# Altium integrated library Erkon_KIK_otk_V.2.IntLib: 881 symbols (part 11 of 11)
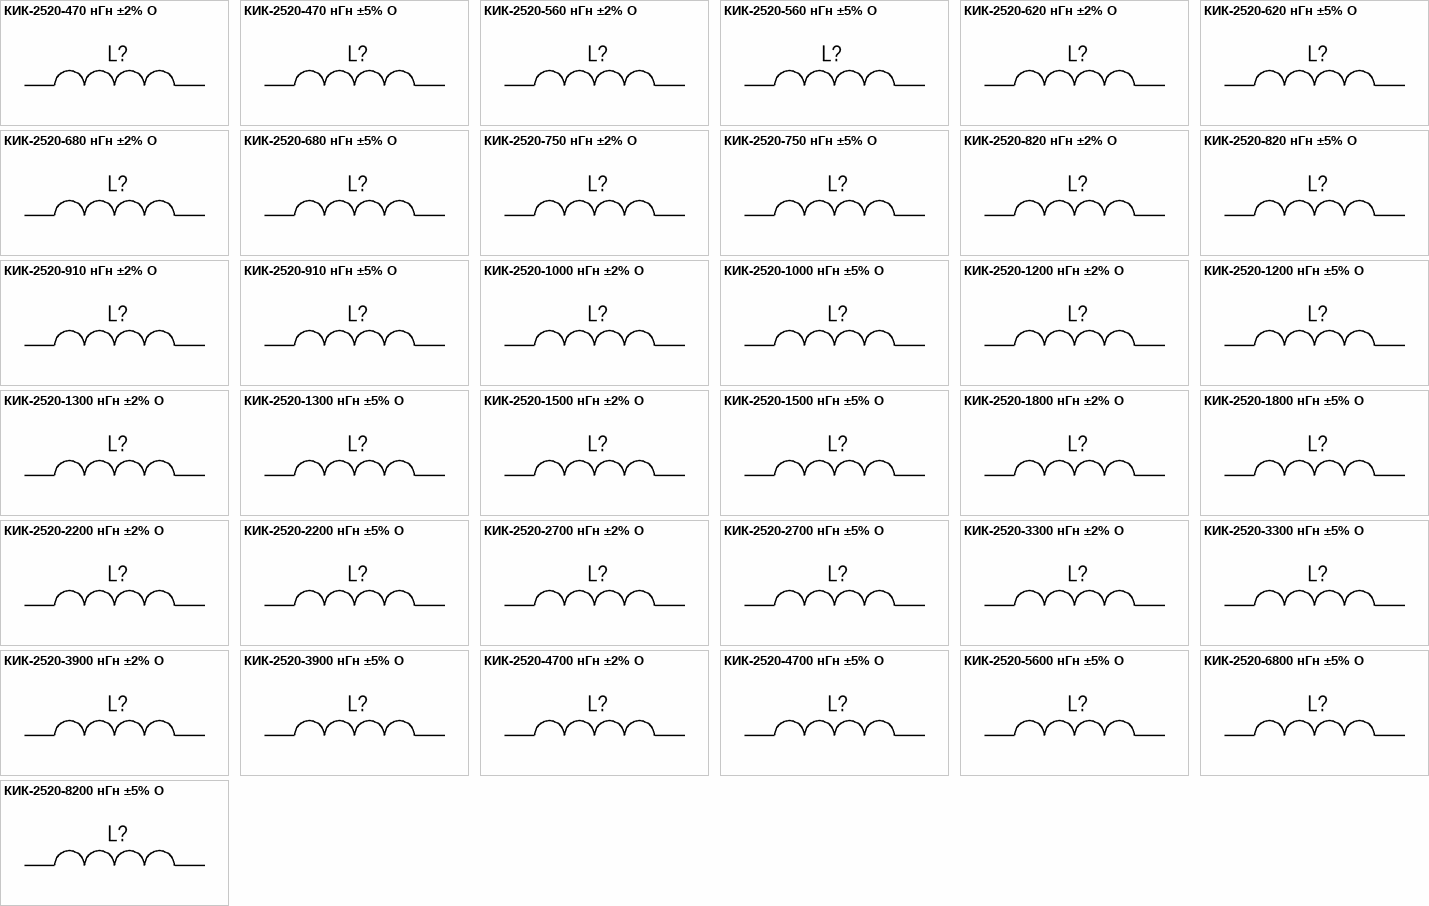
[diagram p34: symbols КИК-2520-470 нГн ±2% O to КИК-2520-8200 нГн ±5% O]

## КИК-2520-820 нГн ±5% O
designator L?, comment 820 нГн ±5%  (value not drawn)
Катушка индуктивности с керамическим сердечником и  финишным покрытием контактных площадок оловом; Номиналиная индуктивность: 820 нГн; Добротность, не менее: 45; Резонансная частота, не менее: 0.350 ГГц; Сопротивление обмотки постоянноми току, не более: 1.61 Ом; Допустимый ток обмотки: 400 мА; Диапазон рабочих температур: от -60 до +125 ℃; Упаковка: Катушка и лента; Типоразмер: 2520 (1008); Технология монтажа: SMT; Изготовитель: АО "НПО "ЭРКОН"
footprint КИК-2520-О (Катушка индуктивности с керамическим сердечником типоразмер 2520(1008))
pins: 1, 2

## КИК-2520-910 нГн ±2% O
designator L?, comment 910 нГн ±2%  (value not drawn)
Катушка индуктивности с керамическим сердечником и  финишным покрытием контактных площадок оловом; Номиналиная индуктивность: 910 нГн; Добротность, не менее: 35; Резонансная частота, не менее: 0.320 ГГц; Сопротивление обмотки постоянноми току, не более: 1.68 Ом; Допустимый ток обмотки: 380 мА; Диапазон рабочих температур: от -60 до +125 ℃; Упаковка: Катушка и лента; Типоразмер: 2520 (1008); Технология монтажа: SMT; Изготовитель: АО "НПО "ЭРКОН"
footprint КИК-2520-О (Катушка индуктивности с керамическим сердечником типоразмер 2520(1008))
pins: 1, 2

## КИК-2520-910 нГн ±5% O
designator L?, comment 910 нГн ±5%  (value not drawn)
Катушка индуктивности с керамическим сердечником и  финишным покрытием контактных площадок оловом; Номиналиная индуктивность: 910 нГн; Добротность, не менее: 35; Резонансная частота, не менее: 0.320 ГГц; Сопротивление обмотки постоянноми току, не более: 1.68 Ом; Допустимый ток обмотки: 380 мА; Диапазон рабочих температур: от -60 до +125 ℃; Упаковка: Катушка и лента; Типоразмер: 2520 (1008); Технология монтажа: SMT; Изготовитель: АО "НПО "ЭРКОН"
footprint КИК-2520-О (Катушка индуктивности с керамическим сердечником типоразмер 2520(1008))
pins: 1, 2

## КИК-2520-1000 нГн ±2% O
designator L?, comment 1000 нГн ±2%  (value not drawn)
Катушка индуктивности с керамическим сердечником и  финишным покрытием контактных площадок оловом; Добротность, не менее: 35; Резонансная частота, не менее: 0.290 ГГц; Сопротивление обмотки постоянноми току, не более: 1.75 Ом; Допустимый ток обмотки: 370 мА; Диапазон рабочих температур: от -60 до +125 ℃; Упаковка: Катушка и лента; Типоразмер: 2520 (1008); Технология монтажа: SMT; Изготовитель: АО "НПО "ЭРКОН"
footprint КИК-2520-О (Катушка индуктивности с керамическим сердечником типоразмер 2520(1008))
pins: 1, 2

## КИК-2520-1000 нГн ±5% O
designator L?, comment 1000 нГн ±5%  (value not drawn)
Катушка индуктивности с керамическим сердечником и  финишным покрытием контактных площадок оловом; Добротность, не менее: 35; Резонансная частота, не менее: 0.290 ГГц; Сопротивление обмотки постоянноми току, не более: 1.75 Ом; Допустимый ток обмотки: 370 мА; Диапазон рабочих температур: от -60 до +125 ℃; Упаковка: Катушка и лента; Типоразмер: 2520 (1008); Технология монтажа: SMT; Изготовитель: АО "НПО "ЭРКОН"
footprint КИК-2520-О (Катушка индуктивности с керамическим сердечником типоразмер 2520(1008))
pins: 1, 2

## КИК-2520-1200 нГн ±2% O
designator L?, comment 1200 нГн ±2%  (value not drawn)
Катушка индуктивности с керамическим сердечником и  финишным покрытием контактных площадок оловом; Добротность, не менее: 35; Резонансная частота, не менее: 0.250 ГГц; Сопротивление обмотки постоянноми току, не более: 2.00 Ом; Допустимый ток обмотки: 310 мА; Диапазон рабочих температур: от -60 до +125 ℃; Упаковка: Катушка и лента; Типоразмер: 2520 (1008); Технология монтажа: SMT; Изготовитель: АО "НПО "ЭРКОН"
footprint КИК-2520-О (Катушка индуктивности с керамическим сердечником типоразмер 2520(1008))
pins: 1, 2

## КИК-2520-1200 нГн ±5% O
designator L?, comment 1200 нГн ±5%  (value not drawn)
Катушка индуктивности с керамическим сердечником и  финишным покрытием контактных площадок оловом; Добротность, не менее: 35; Резонансная частота, не менее: 0.250 ГГц; Сопротивление обмотки постоянноми току, не более: 2.00 Ом; Допустимый ток обмотки: 310 мА; Диапазон рабочих температур: от -60 до +125 ℃; Упаковка: Катушка и лента; Типоразмер: 2520 (1008); Технология монтажа: SMT; Изготовитель: АО "НПО "ЭРКОН"
footprint КИК-2520-О (Катушка индуктивности с керамическим сердечником типоразмер 2520(1008))
pins: 1, 2

## КИК-2520-1300 нГн ±2% O
designator L?, comment 1300 нГн ±2%  (value not drawn)
Катушка индуктивности с керамическим сердечником и  финишным покрытием контактных площадок оловом; Добротность, не менее: 25; Резонансная частота, не менее: 0.200 ГГц; Сопротивление обмотки постоянноми току, не более: 2.25 Ом; Допустимый ток обмотки: 310 мА; Диапазон рабочих температур: от -60 до +125 ℃; Упаковка: Катушка и лента; Типоразмер: 2520 (1008); Технология монтажа: SMT; Изготовитель: АО "НПО "ЭРКОН"
footprint КИК-2520-О (Катушка индуктивности с керамическим сердечником типоразмер 2520(1008))
pins: 1, 2

## КИК-2520-1300 нГн ±5% O
designator L?, comment 1300 нГн ±5%  (value not drawn)
Катушка индуктивности с керамическим сердечником и  финишным покрытием контактных площадок оловом; Добротность, не менее: 25; Резонансная частота, не менее: 0.200 ГГц; Сопротивление обмотки постоянноми току, не более: 2.25 Ом; Допустимый ток обмотки: 310 мА; Диапазон рабочих температур: от -60 до +125 ℃; Упаковка: Катушка и лента; Типоразмер: 2520 (1008); Технология монтажа: SMT; Изготовитель: АО "НПО "ЭРКОН"
footprint КИК-2520-О (Катушка индуктивности с керамическим сердечником типоразмер 2520(1008))
pins: 1, 2

## КИК-2520-1500 нГн ±2% O
designator L?, comment 1500 нГн ±2%  (value not drawn)
Катушка индуктивности с керамическим сердечником и  финишным покрытием контактных площадок оловом; Номиналиная индуктивность: 1300 нГн; Добротность, не менее: 28; Резонансная частота, не менее: 0.200 ГГц; Сопротивление обмотки постоянноми току, не более: 2.30 Ом; Допустимый ток обмотки: 330 мА; Диапазон рабочих температур: от -60 до +125 ℃; Упаковка: Катушка и лента; Типоразмер: 2520 (1008); Технология монтажа: SMT; Изготовитель: АО "НПО "ЭРКОН"
footprint КИК-2520-О (Катушка индуктивности с керамическим сердечником типоразмер 2520(1008))
pins: 1, 2

## КИК-2520-1500 нГн ±5% O
designator L?, comment 1500 нГн ±5%  (value not drawn)
Катушка индуктивности с керамическим сердечником и  финишным покрытием контактных площадок оловом; Номиналиная индуктивность: 1300 нГн; Добротность, не менее: 28; Резонансная частота, не менее: 0.200 ГГц; Сопротивление обмотки постоянноми току, не более: 2.30 Ом; Допустимый ток обмотки: 330 мА; Диапазон рабочих температур: от -60 до +125 ℃; Упаковка: Катушка и лента; Типоразмер: 2520 (1008); Технология монтажа: SMT; Изготовитель: АО "НПО "ЭРКОН"
footprint КИК-2520-О (Катушка индуктивности с керамическим сердечником типоразмер 2520(1008))
pins: 1, 2

## КИК-2520-1800 нГн ±2% O
designator L?, comment 1800 нГн ±2%  (value not drawn)
Катушка индуктивности с керамическим сердечником и  финишным покрытием контактных площадок оловом; Добротность, не менее: 28; Резонансная частота, не менее: 0.160 ГГц; Сопротивление обмотки постоянноми току, не более: 2.60 Ом; Допустимый ток обмотки: 300 мА; Диапазон рабочих температур: от -60 до +125 ℃; Упаковка: Катушка и лента; Типоразмер: 2520 (1008); Технология монтажа: SMT; Изготовитель: АО "НПО "ЭРКОН"
footprint КИК-2520-О (Катушка индуктивности с керамическим сердечником типоразмер 2520(1008))
pins: 1, 2

## КИК-2520-1800 нГн ±5% O
designator L?, comment 1800 нГн ±5%  (value not drawn)
Катушка индуктивности с керамическим сердечником и  финишным покрытием контактных площадок оловом; Добротность, не менее: 28; Резонансная частота, не менее: 0.160 ГГц; Сопротивление обмотки постоянноми току, не более: 2.60 Ом; Допустимый ток обмотки: 300 мА; Диапазон рабочих температур: от -60 до +125 ℃; Упаковка: Катушка и лента; Типоразмер: 2520 (1008); Технология монтажа: SMT; Изготовитель: АО "НПО "ЭРКОН"
footprint КИК-2520-О (Катушка индуктивности с керамическим сердечником типоразмер 2520(1008))
pins: 1, 2

## КИК-2520-2200 нГн ±2% O
designator L?, comment 2200 нГн ±2%  (value not drawn)
Катушка индуктивности с керамическим сердечником и  финишным покрытием контактных площадок оловом; Добротность, не менее: 28; Резонансная частота, не менее: 0.160 ГГц; Сопротивление обмотки постоянноми току, не более: 2.80 Ом; Допустимый ток обмотки: 280 мА; Диапазон рабочих температур: от -60 до +125 ℃; Упаковка: Катушка и лента; Типоразмер: 2520 (1008); Технология монтажа: SMT; Изготовитель: АО "НПО "ЭРКОН"
footprint КИК-2520-О (Катушка индуктивности с керамическим сердечником типоразмер 2520(1008))
pins: 1, 2

## КИК-2520-2200 нГн ±5% O
designator L?, comment 2200 нГн ±5%  (value not drawn)
Катушка индуктивности с керамическим сердечником и  финишным покрытием контактных площадок оловом; Добротность, не менее: 28; Резонансная частота, не менее: 0.160 ГГц; Сопротивление обмотки постоянноми току, не более: 2.80 Ом; Допустимый ток обмотки: 280 мА; Диапазон рабочих температур: от -60 до +125 ℃; Упаковка: Катушка и лента; Типоразмер: 2520 (1008); Технология монтажа: SMT; Изготовитель: АО "НПО "ЭРКОН"
footprint КИК-2520-О (Катушка индуктивности с керамическим сердечником типоразмер 2520(1008))
pins: 1, 2

## КИК-2520-2700 нГн ±2% O
designator L?, comment 2700 нГн ±2%  (value not drawn)
Катушка индуктивности с керамическим сердечником и  финишным покрытием контактных площадок оловом; Добротность, не менее: 22; Резонансная частота, не менее: 0.140 ГГц; Сопротивление обмотки постоянноми току, не более: 3.20 Ом; Допустимый ток обмотки: 290 мА; Диапазон рабочих температур: от -60 до +125 ℃; Упаковка: Катушка и лента; Типоразмер: 2520 (1008); Технология монтажа: SMT; Изготовитель: АО "НПО "ЭРКОН"
footprint КИК-2520-О (Катушка индуктивности с керамическим сердечником типоразмер 2520(1008))
pins: 1, 2

## КИК-2520-2700 нГн ±5% O
designator L?, comment 2700 нГн ±5%  (value not drawn)
Катушка индуктивности с керамическим сердечником и  финишным покрытием контактных площадок оловом; Добротность, не менее: 22; Резонансная частота, не менее: 0.140 ГГц; Сопротивление обмотки постоянноми току, не более: 3.20 Ом; Допустимый ток обмотки: 290 мА; Диапазон рабочих температур: от -60 до +125 ℃; Упаковка: Катушка и лента; Типоразмер: 2520 (1008); Технология монтажа: SMT; Изготовитель: АО "НПО "ЭРКОН"
footprint КИК-2520-О (Катушка индуктивности с керамическим сердечником типоразмер 2520(1008))
pins: 1, 2

## КИК-2520-3300 нГн ±2% O
designator L?, comment 3300 нГн ±2%  (value not drawn)
Катушка индуктивности с керамическим сердечником и  финишным покрытием контактных площадок оловом; Добротность, не менее: 22; Резонансная частота, не менее: 0.110 ГГц; Сопротивление обмотки постоянноми току, не более: 3.40 Ом; Допустимый ток обмотки: 290 мА; Диапазон рабочих температур: от -60 до +125 ℃; Упаковка: Катушка и лента; Типоразмер: 2520 (1008); Технология монтажа: SMT; Изготовитель: АО "НПО "ЭРКОН"
footprint КИК-2520-О (Катушка индуктивности с керамическим сердечником типоразмер 2520(1008))
pins: 1, 2

## КИК-2520-3300 нГн ±5% O
designator L?, comment 3300 нГн ±5%  (value not drawn)
Катушка индуктивности с керамическим сердечником и  финишным покрытием контактных площадок оловом; Добротность, не менее: 22; Резонансная частота, не менее: 0.110 ГГц; Сопротивление обмотки постоянноми току, не более: 3.40 Ом; Допустимый ток обмотки: 290 мА; Диапазон рабочих температур: от -60 до +125 ℃; Упаковка: Катушка и лента; Типоразмер: 2520 (1008); Технология монтажа: SMT; Изготовитель: АО "НПО "ЭРКОН"
footprint КИК-2520-О (Катушка индуктивности с керамическим сердечником типоразмер 2520(1008))
pins: 1, 2

## КИК-2520-3900 нГн ±2% O
designator L?, comment 3900 нГн ±2%  (value not drawn)
Катушка индуктивности с керамическим сердечником и  финишным покрытием контактных площадок оловом; Добротность, не менее: 20; Резонансная частота, не менее: 0.100 ГГц; Сопротивление обмотки постоянноми току, не более: 3.60 Ом; Допустимый ток обмотки: 260 мА; Диапазон рабочих температур: от -60 до +125 ℃; Упаковка: Катушка и лента; Типоразмер: 2520 (1008); Технология монтажа: SMT; Изготовитель: АО "НПО "ЭРКОН"
footprint КИК-2520-О (Катушка индуктивности с керамическим сердечником типоразмер 2520(1008))
pins: 1, 2

## КИК-2520-3900 нГн ±5% O
designator L?, comment 3900 нГн ±5%  (value not drawn)
Катушка индуктивности с керамическим сердечником и  финишным покрытием контактных площадок оловом; Добротность, не менее: 20; Резонансная частота, не менее: 0.100 ГГц; Сопротивление обмотки постоянноми току, не более: 3.60 Ом; Допустимый ток обмотки: 260 мА; Диапазон рабочих температур: от -60 до +125 ℃; Упаковка: Катушка и лента; Типоразмер: 2520 (1008); Технология монтажа: SMT; Изготовитель: АО "НПО "ЭРКОН"
footprint КИК-2520-О (Катушка индуктивности с керамическим сердечником типоразмер 2520(1008))
pins: 1, 2

## КИК-2520-4700 нГн ±2% O
designator L?, comment 4700 нГн ±2%  (value not drawn)
Катушка индуктивности с керамическим сердечником и  финишным покрытием контактных площадок оловом; Добротность, не менее: 20; Резонансная частота, не менее: 0.090 ГГц; Сопротивление обмотки постоянноми току, не более: 4.00 Ом; Допустимый ток обмотки: 260 мА; Диапазон рабочих температур: от -60 до +125 ℃; Упаковка: Катушка и лента; Типоразмер: 2520 (1008); Технология монтажа: SMT; Изготовитель: АО "НПО "ЭРКОН"
footprint КИК-2520-О (Катушка индуктивности с керамическим сердечником типоразмер 2520(1008))
pins: 1, 2

## КИК-2520-4700 нГн ±5% O
designator L?, comment 4700 нГн ±5%  (value not drawn)
Катушка индуктивности с керамическим сердечником и  финишным покрытием контактных площадок оловом; Добротность, не менее: 20; Резонансная частота, не менее: 0.090 ГГц; Сопротивление обмотки постоянноми току, не более: 4.00 Ом; Допустимый ток обмотки: 260 мА; Диапазон рабочих температур: от -60 до +125 ℃; Упаковка: Катушка и лента; Типоразмер: 2520 (1008); Технология монтажа: SMT; Изготовитель: АО "НПО "ЭРКОН"
footprint КИК-2520-О (Катушка индуктивности с керамическим сердечником типоразмер 2520(1008))
pins: 1, 2

## КИК-2520-5600 нГн ±5% O
designator L?, comment 5600 нГн ±5%  (value not drawn)
Катушка индуктивности с керамическим сердечником и  финишным покрытием контактных площадок оловом; Добротность, не менее: 16; Резонансная частота, не менее: 0.020 ГГц; Сопротивление обмотки постоянноми току, не более: 4.00 Ом; Допустимый ток обмотки: 240 мА; Диапазон рабочих температур: от -60 до +125 ℃; Упаковка: Катушка и лента; Типоразмер: 2520 (1008); Технология монтажа: SMT; Изготовитель: АО "НПО "ЭРКОН"
footprint КИК-2520-О (Катушка индуктивности с керамическим сердечником типоразмер 2520(1008))
pins: 1, 2

## КИК-2520-6800 нГн ±5% O
designator L?, comment 6800 нГн ±5%  (value not drawn)
Катушка индуктивности с керамическим сердечником и  финишным покрытием контактных площадок оловом; Добротность, не менее: 18; Резонансная частота, не менее: 0.040 ГГц; Сопротивление обмотки постоянноми току, не более: 4.90 Ом; Допустимый ток обмотки: 200 мА; Диапазон рабочих температур: от -60 до +125 ℃; Упаковка: Катушка и лента; Типоразмер: 2520 (1008); Технология монтажа: SMT; Изготовитель: АО "НПО "ЭРКОН"
footprint КИК-2520-О (Катушка индуктивности с керамическим сердечником типоразмер 2520(1008))
pins: 1, 2

## КИК-2520-8200 нГн ±5% O
designator L?, comment 8200 нГн ±5%  (value not drawn)
Катушка индуктивности с керамическим сердечником и  финишным покрытием контактных площадок оловом; Добротность, не менее: 18; Резонансная частота, не менее: 0.025 ГГц; Сопротивление обмотки постоянноми току, не более: 6.00 Ом; Допустимый ток обмотки: 170 мА; Диапазон рабочих температур: от -60 до +125 ℃; Упаковка: Катушка и лента; Типоразмер: 2520 (1008); Технология монтажа: SMT; Изготовитель: АО "НПО "ЭРКОН"
footprint КИК-2520-О (Катушка индуктивности с керамическим сердечником типоразмер 2520(1008))
pins: 1, 2


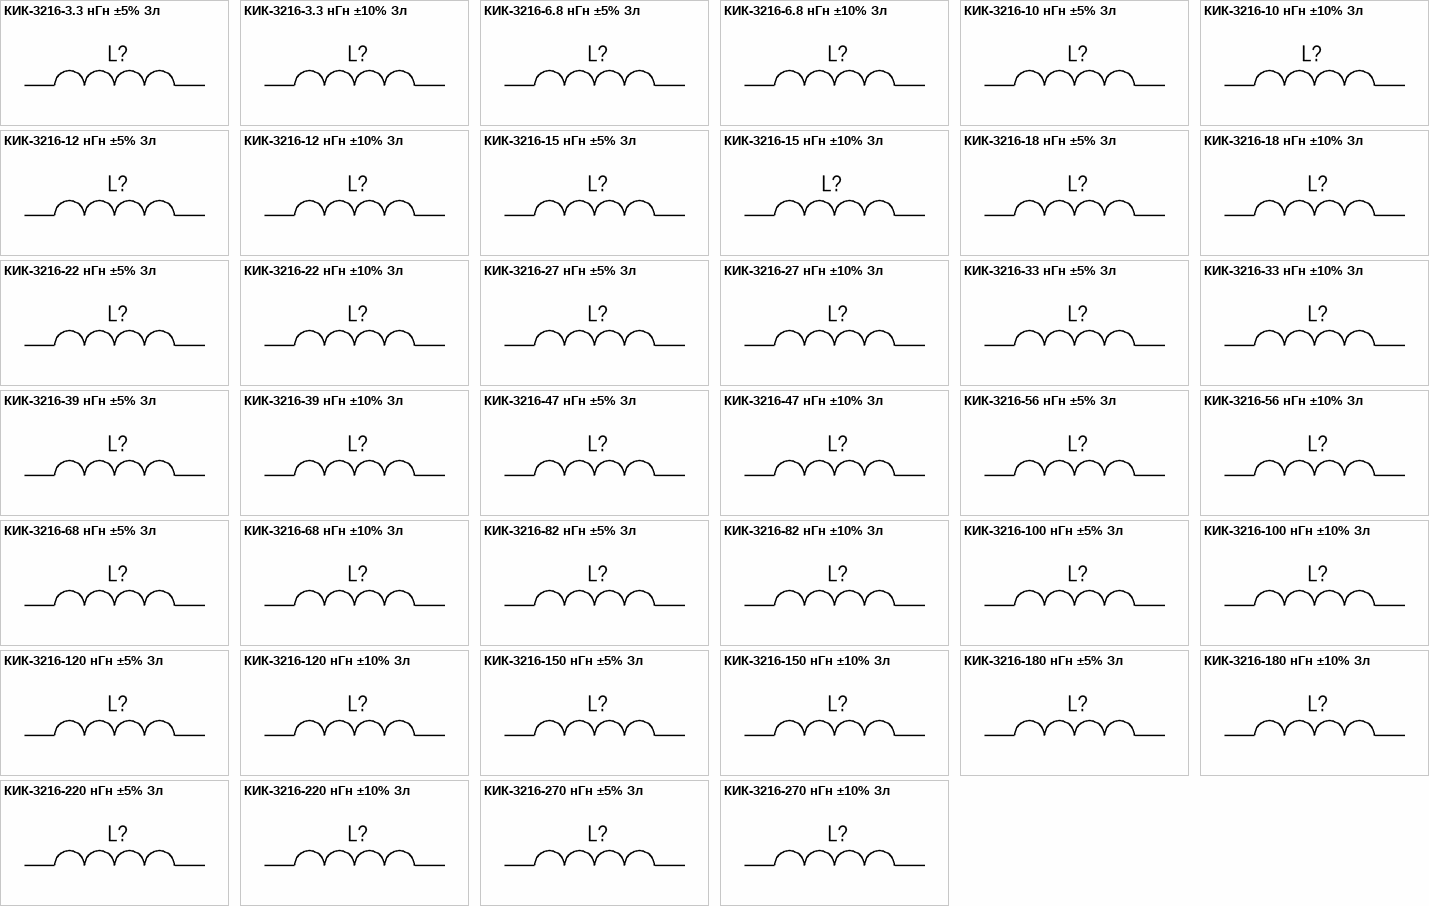
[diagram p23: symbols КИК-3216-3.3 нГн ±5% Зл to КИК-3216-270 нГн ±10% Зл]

## КИК-3216-3.3 нГн ±5% Зл
designator L?, comment 3.3 нГн ±5%  (value not drawn)
Катушка индуктивности с керамическим сердечником и золотым покрытием контактных площадок; Номиналиная индуктивность: 3.3 нГн; Добротность, не менее: 30; Резонансная частота, не менее: 6.20 ГГц; Сопротивление обмотки постоянноми току, не более: 0.05 Ом; Допустимый ток обмотки: 1000 мА; Диапазон рабочих температур: от -60 до +125 ℃; Упаковка: Катушка и лента; Типоразмер: 3216 (1206); Технология монтажа: SMT; Изготовитель: АО "НПО "ЭРКОН"
pins: 1, 2

## КИК-3216-3.3 нГн ±10% Зл
designator L?, comment 3.3 нГн ±10%  (value not drawn)
Катушка индуктивности с керамическим сердечником и золотым покрытием контактных площадок; Номиналиная индуктивность: 3.3 нГн; Добротность, не менее: 30; Резонансная частота, не менее: 6.20 ГГц; Сопротивление обмотки постоянноми току, не более: 0.05 Ом; Допустимый ток обмотки: 1000 мА; Диапазон рабочих температур: от -60 до +125 ℃; Упаковка: Катушка и лента; Типоразмер: 3216 (1206); Технология монтажа: SMT; Изготовитель: АО "НПО "ЭРКОН"
pins: 1, 2

## КИК-3216-6.8 нГн ±5% Зл
designator L?, comment 6.8 нГн ±5%  (value not drawn)
Катушка индуктивности с керамическим сердечником и золотым покрытием контактных площадок; Номиналиная индуктивность: 6.8 нГн; Добротность, не менее: 30; Резонансная частота, не менее: 5.50 ГГц; Сопротивление обмотки постоянноми току, не более: 0.07 Ом; Допустимый ток обмотки: 1000 мА; Диапазон рабочих температур: от -60 до +125 ℃; Упаковка: Катушка и лента; Типоразмер: 3216 (1206); Технология монтажа: SMT; Изготовитель: АО "НПО "ЭРКОН"
pins: 1, 2

## КИК-3216-6.8 нГн ±10% Зл
designator L?, comment 6.8 нГн ±10%  (value not drawn)
Катушка индуктивности с керамическим сердечником и золотым покрытием контактных площадок; Номиналиная индуктивность: 6.8 нГн; Добротность, не менее: 30; Резонансная частота, не менее: 5.50 ГГц; Сопротивление обмотки постоянноми току, не более: 0.07 Ом; Допустимый ток обмотки: 1000 мА; Диапазон рабочих температур: от -60 до +125 ℃; Упаковка: Катушка и лента; Типоразмер: 3216 (1206); Технология монтажа: SMT; Изготовитель: АО "НПО "ЭРКОН"
pins: 1, 2

## КИК-3216-10 нГн ±5% Зл
designator L?, comment 10 нГн ±5%  (value not drawn)
Катушка индуктивности с керамическим сердечником и золотым покрытием контактных площадок; Номиналиная индуктивность: 10 нГн; Добротность, не менее: 40; Резонансная частота, не менее: 4.0 ГГц; Сопротивление обмотки постоянноми току, не более: 0.08 Ом; Допустимый ток обмотки: 1000 мА; Диапазон рабочих температур: от -60 до +125 ℃; Упаковка: Катушка и лента; Типоразмер: 3216 (1206); Технология монтажа: SMT; Изготовитель: АО "НПО "ЭРКОН"
pins: 1, 2

## КИК-3216-10 нГн ±10% Зл
designator L?, comment 10 нГн ±10%  (value not drawn)
Катушка индуктивности с керамическим сердечником и золотым покрытием контактных площадок; Номиналиная индуктивность: 10 нГн; Добротность, не менее: 40; Резонансная частота, не менее: 4.0 ГГц; Сопротивление обмотки постоянноми току, не более: 0.08 Ом; Допустимый ток обмотки: 1000 мА; Диапазон рабочих температур: от -60 до +125 ℃; Упаковка: Катушка и лента; Типоразмер: 3216 (1206); Технология монтажа: SMT; Изготовитель: АО "НПО "ЭРКОН"
pins: 1, 2

## КИК-3216-12 нГн ±5% Зл
designator L?, comment 12 нГн ±5%  (value not drawn)
Катушка индуктивности с керамическим сердечником и золотым покрытием контактных площадок; Номиналиная индуктивность: 12 нГн; Добротность, не менее: 40; Резонансная частота, не менее: 3.20 ГГц; Сопротивление обмотки постоянноми току, не более: 0.08 Ом; Допустимый ток обмотки: 1000 мА; Диапазон рабочих температур: от -60 до +125 ℃; Упаковка: Катушка и лента; Типоразмер: 3216 (1206); Технология монтажа: SMT; Изготовитель: АО "НПО "ЭРКОН"
pins: 1, 2

## КИК-3216-12 нГн ±10% Зл
designator L?, comment 12 нГн ±10%  (value not drawn)
Катушка индуктивности с керамическим сердечником и золотым покрытием контактных площадок; Номиналиная индуктивность: 12 нГн; Добротность, не менее: 40; Резонансная частота, не менее: 3.20 ГГц; Сопротивление обмотки постоянноми току, не более: 0.08 Ом; Допустимый ток обмотки: 1000 мА; Диапазон рабочих температур: от -60 до +125 ℃; Упаковка: Катушка и лента; Типоразмер: 3216 (1206); Технология монтажа: SMT; Изготовитель: АО "НПО "ЭРКОН"
pins: 1, 2

## КИК-3216-15 нГн ±5% Зл
designator L?, comment 15 нГн ±5%  (value not drawn)
Катушка индуктивности с керамическим сердечником и золотым покрытием контактных площадок; Номиналиная индуктивность: 15 нГн; Добротность, не менее: 40; Резонансная частота, не менее: 3.20 ГГц; Сопротивление обмотки постоянноми току, не более: 0.10 Ом; Допустимый ток обмотки: 1000 мА; Диапазон рабочих температур: от -60 до +125 ℃; Упаковка: Катушка и лента; Типоразмер: 3216 (1206); Технология монтажа: SMT; Изготовитель: АО "НПО "ЭРКОН"
pins: 1, 2

## КИК-3216-15 нГн ±10% Зл
designator L?, comment 15 нГн ±10%  (value not drawn)
Катушка индуктивности с керамическим сердечником и золотым покрытием контактных площадок; Номиналиная индуктивность: 15 нГн; Добротность, не менее: 40; Резонансная частота, не менее: 3.20 ГГц; Сопротивление обмотки постоянноми току, не более: 0.10 Ом; Допустимый ток обмотки: 1000 мА; Диапазон рабочих температур: от -60 до +125 ℃; Упаковка: Катушка и лента; Типоразмер: 3216 (1206); Технология монтажа: SMT; Изготовитель: АО "НПО "ЭРКОН"
pins: 1, 2

## КИК-3216-18 нГн ±5% Зл
designator L?, comment 18 нГн ±5%  (value not drawn)
Катушка индуктивности с керамическим сердечником и золотым покрытием контактных площадок; Номиналиная индуктивность: 18 нГн; Добротность, не менее: 50; Резонансная частота, не менее: 2.80 ГГц; Сопротивление обмотки постоянноми току, не более: 0.10 Ом; Допустимый ток обмотки: 1000 мА; Диапазон рабочих температур: от -60 до +125 ℃; Упаковка: Катушка и лента; Типоразмер: 3216 (1206); Технология монтажа: SMT; Изготовитель: АО "НПО "ЭРКОН"
pins: 1, 2

## КИК-3216-18 нГн ±10% Зл
designator L?, comment 18 нГн ±10%  (value not drawn)
Катушка индуктивности с керамическим сердечником и золотым покрытием контактных площадок; Номиналиная индуктивность: 18 нГн; Добротность, не менее: 50; Резонансная частота, не менее: 2.80 ГГц; Сопротивление обмотки постоянноми току, не более: 0.10 Ом; Допустимый ток обмотки: 1000 мА; Диапазон рабочих температур: от -60 до +125 ℃; Упаковка: Катушка и лента; Типоразмер: 3216 (1206); Технология монтажа: SMT; Изготовитель: АО "НПО "ЭРКОН"
pins: 1, 2

## КИК-3216-22 нГн ±5% Зл
designator L?, comment 22 нГн ±5%  (value not drawn)
Катушка индуктивности с керамическим сердечником и золотым покрытием контактных площадок; Номиналиная индуктивность: 22 нГн; Добротность, не менее: 50; Резонансная частота, не менее: 2.20 ГГц; Сопротивление обмотки постоянноми току, не более: 0.10 Ом; Допустимый ток обмотки: 1000 мА; Диапазон рабочих температур: от -60 до +125 ℃; Упаковка: Катушка и лента; Типоразмер: 3216 (1206); Технология монтажа: SMT; Изготовитель: АО "НПО "ЭРКОН"
pins: 1, 2

## КИК-3216-22 нГн ±10% Зл
designator L?, comment 22 нГн ±10%  (value not drawn)
Катушка индуктивности с керамическим сердечником и золотым покрытием контактных площадок; Номиналиная индуктивность: 22 нГн; Добротность, не менее: 50; Резонансная частота, не менее: 2.20 ГГц; Сопротивление обмотки постоянноми току, не более: 0.10 Ом; Допустимый ток обмотки: 1000 мА; Диапазон рабочих температур: от -60 до +125 ℃; Упаковка: Катушка и лента; Типоразмер: 3216 (1206); Технология монтажа: SMT; Изготовитель: АО "НПО "ЭРКОН"
pins: 1, 2

## КИК-3216-27 нГн ±5% Зл
designator L?, comment 27 нГн ±5%  (value not drawn)
Катушка индуктивности с керамическим сердечником и золотым покрытием контактных площадок; Номиналиная индуктивность: 27 нГн; Добротность, не менее: 50; Резонансная частота, не менее: 1.80 ГГц; Сопротивление обмотки постоянноми току, не более: 0.11 Ом; Допустимый ток обмотки: 1000 мА; Диапазон рабочих температур: от -60 до +125 ℃; Упаковка: Катушка и лента; Типоразмер: 3216 (1206); Технология монтажа: SMT; Изготовитель: АО "НПО "ЭРКОН"
pins: 1, 2

## КИК-3216-27 нГн ±10% Зл
designator L?, comment 27 нГн ±10%  (value not drawn)
Катушка индуктивности с керамическим сердечником и золотым покрытием контактных площадок; Номиналиная индуктивность: 27 нГн; Добротность, не менее: 50; Резонансная частота, не менее: 1.80 ГГц; Сопротивление обмотки постоянноми току, не более: 0.11 Ом; Допустимый ток обмотки: 1000 мА; Диапазон рабочих температур: от -60 до +125 ℃; Упаковка: Катушка и лента; Типоразмер: 3216 (1206); Технология монтажа: SMT; Изготовитель: АО "НПО "ЭРКОН"
pins: 1, 2

## КИК-3216-33 нГн ±5% Зл
designator L?, comment 33 нГн ±5%  (value not drawn)
Катушка индуктивности с керамическим сердечником и золотым покрытием контактных площадок; Номиналиная индуктивность: 33 нГн; Добротность, не менее: 55; Резонансная частота, не менее: 1.80 ГГц; Сопротивление обмотки постоянноми току, не более: 0.11 Ом; Допустимый ток обмотки: 1000 мА; Диапазон рабочих температур: от -60 до +125 ℃; Упаковка: Катушка и лента; Типоразмер: 3216 (1206); Технология монтажа: SMT; Изготовитель: АО "НПО "ЭРКОН"
pins: 1, 2

## КИК-3216-33 нГн ±10% Зл
designator L?, comment 33 нГн ±10%  (value not drawn)
Катушка индуктивности с керамическим сердечником и золотым покрытием контактных площадок; Номиналиная индуктивность: 33 нГн; Добротность, не менее: 55; Резонансная частота, не менее: 1.80 ГГц; Сопротивление обмотки постоянноми току, не более: 0.11 Ом; Допустимый ток обмотки: 1000 мА; Диапазон рабочих температур: от -60 до +125 ℃; Упаковка: Катушка и лента; Типоразмер: 3216 (1206); Технология монтажа: SMT; Изготовитель: АО "НПО "ЭРКОН"
pins: 1, 2

## КИК-3216-39 нГн ±5% Зл
designator L?, comment 39 нГн ±5%  (value not drawn)
Катушка индуктивности с керамическим сердечником и золотым покрытием контактных площадок; Номиналиная индуктивность: 39 нГн; Добротность, не менее: 55; Резонансная частота, не менее: 1.80 ГГц; Сопротивление обмотки постоянноми току, не более: 0.12 Ом; Допустимый ток обмотки: 1000 мА; Диапазон рабочих температур: от -60 до +125 ℃; Упаковка: Катушка и лента; Типоразмер: 3216 (1206); Технология монтажа: SMT; Изготовитель: АО "НПО "ЭРКОН"
pins: 1, 2

## КИК-3216-39 нГн ±10% Зл
designator L?, comment 39 нГн ±10%  (value not drawn)
Катушка индуктивности с керамическим сердечником и золотым покрытием контактных площадок; Номиналиная индуктивность: 39 нГн; Добротность, не менее: 55; Резонансная частота, не менее: 1.80 ГГц; Сопротивление обмотки постоянноми току, не более: 0.12 Ом; Допустимый ток обмотки: 1000 мА; Диапазон рабочих температур: от -60 до +125 ℃; Упаковка: Катушка и лента; Типоразмер: 3216 (1206); Технология монтажа: SMT; Изготовитель: АО "НПО "ЭРКОН"
pins: 1, 2

## КИК-3216-47 нГн ±5% Зл
designator L?, comment 47 нГн ±5%  (value not drawn)
Катушка индуктивности с керамическим сердечником и золотым покрытием контактных площадок; Номиналиная индуктивность: 47 нГн; Добротность, не менее: 55; Резонансная частота, не менее: 1.50 ГГц; Сопротивление обмотки постоянноми току, не более: 0.13 Ом; Допустимый ток обмотки: 1000 мА; Диапазон рабочих температур: от -60 до +125 ℃; Упаковка: Катушка и лента; Типоразмер: 3216 (1206); Технология монтажа: SMT; Изготовитель: АО "НПО "ЭРКОН"
pins: 1, 2

## КИК-3216-47 нГн ±10% Зл
designator L?, comment 47 нГн ±10%  (value not drawn)
Катушка индуктивности с керамическим сердечником и золотым покрытием контактных площадок; Номиналиная индуктивность: 47 нГн; Добротность, не менее: 55; Резонансная частота, не менее: 1.50 ГГц; Сопротивление обмотки постоянноми току, не более: 0.13 Ом; Допустимый ток обмотки: 1000 мА; Диапазон рабочих температур: от -60 до +125 ℃; Упаковка: Катушка и лента; Типоразмер: 3216 (1206); Технология монтажа: SMT; Изготовитель: АО "НПО "ЭРКОН"
pins: 1, 2

## КИК-3216-56 нГн ±5% Зл
designator L?, comment 56 нГн ±5%  (value not drawn)
Катушка индуктивности с керамическим сердечником и золотым покрытием контактных площадок; Номиналиная индуктивность: 56 нГн; Добротность, не менее: 55; Резонансная частота, не менее: 1.45 ГГц; Сопротивление обмотки постоянноми току, не более: 0.14 Ом; Допустимый ток обмотки: 1000 мА; Диапазон рабочих температур: от -60 до +125 ℃; Упаковка: Катушка и лента; Типоразмер: 3216 (1206); Технология монтажа: SMT; Изготовитель: АО "НПО "ЭРКОН"
pins: 1, 2

## КИК-3216-56 нГн ±10% Зл
designator L?, comment 56 нГн ±10%  (value not drawn)
Катушка индуктивности с керамическим сердечником и золотым покрытием контактных площадок; Номиналиная индуктивность: 56 нГн; Добротность, не менее: 55; Резонансная частота, не менее: 1.45 ГГц; Сопротивление обмотки постоянноми току, не более: 0.14 Ом; Допустимый ток обмотки: 1000 мА; Диапазон рабочих температур: от -60 до +125 ℃; Упаковка: Катушка и лента; Типоразмер: 3216 (1206); Технология монтажа: SMT; Изготовитель: АО "НПО "ЭРКОН"
pins: 1, 2

## КИК-3216-68 нГн ±5% Зл
designator L?, comment 68 нГн ±5%  (value not drawn)
Катушка индуктивности с керамическим сердечником и золотым покрытием контактных площадок; Номиналиная индуктивность: 68 нГн; Добротность, не менее: 55; Резонансная частота, не менее: 1.20 ГГц; Сопротивление обмотки постоянноми току, не более: 0.26 Ом; Допустимый ток обмотки: 900 мА; Диапазон рабочих температур: от -60 до +125 ℃; Упаковка: Катушка и лента; Типоразмер: 3216 (1206); Технология монтажа: SMT; Изготовитель: АО "НПО "ЭРКОН"
pins: 1, 2

## КИК-3216-68 нГн ±10% Зл
designator L?, comment 68 нГн ±10%  (value not drawn)
Катушка индуктивности с керамическим сердечником и золотым покрытием контактных площадок; Номиналиная индуктивность: 68 нГн; Добротность, не менее: 55; Резонансная частота, не менее: 1.20 ГГц; Сопротивление обмотки постоянноми току, не более: 0.26 Ом; Допустимый ток обмотки: 900 мА; Диапазон рабочих температур: от -60 до +125 ℃; Упаковка: Катушка и лента; Типоразмер: 3216 (1206); Технология монтажа: SMT; Изготовитель: АО "НПО "ЭРКОН"
pins: 1, 2

## КИК-3216-82 нГн ±5% Зл
designator L?, comment 82 нГн ±5%  (value not drawn)
Катушка индуктивности с керамическим сердечником и золотым покрытием контактных площадок; Номиналиная индуктивность: 82 нГн; Добротность, не менее: 55; Резонансная частота, не менее: 1.20 ГГц; Сопротивление обмотки постоянноми току, не более: 0.21 Ом; Допустимый ток обмотки: 900 мА; Диапазон рабочих температур: от -60 до +125 ℃; Упаковка: Катушка и лента; Типоразмер: 3216 (1206); Технология монтажа: SMT; Изготовитель: АО "НПО "ЭРКОН"
pins: 1, 2

## КИК-3216-82 нГн ±10% Зл
designator L?, comment 82 нГн ±10%  (value not drawn)
Катушка индуктивности с керамическим сердечником и золотым покрытием контактных площадок; Номиналиная индуктивность: 82 нГн; Добротность, не менее: 55; Резонансная частота, не менее: 1.20 ГГц; Сопротивление обмотки постоянноми току, не более: 0.21 Ом; Допустимый ток обмотки: 900 мА; Диапазон рабочих температур: от -60 до +125 ℃; Упаковка: Катушка и лента; Типоразмер: 3216 (1206); Технология монтажа: SMT; Изготовитель: АО "НПО "ЭРКОН"
pins: 1, 2

## КИК-3216-100 нГн ±5% Зл
designator L?, comment 100 нГн ±5%  (value not drawn)
Катушка индуктивности с керамическим сердечником и золотым покрытием контактных площадок; Номиналиная индуктивность: 100 нГн; Добротность, не менее: 55; Резонансная частота, не менее: 1.10 ГГц; Сопротивление обмотки постоянноми току, не более: 0.26 Ом; Допустимый ток обмотки: 850 мА; Диапазон рабочих температур: от -60 до +125 ℃; Упаковка: Катушка и лента; Типоразмер: 3216 (1206); Технология монтажа: SMT; Изготовитель: АО "НПО "ЭРКОН"
pins: 1, 2

## КИК-3216-100 нГн ±10% Зл
designator L?, comment 100 нГн ±10%  (value not drawn)
Катушка индуктивности с керамическим сердечником и золотым покрытием контактных площадок; Номиналиная индуктивность: 100 нГн; Добротность, не менее: 55; Резонансная частота, не менее: 1.10 ГГц; Сопротивление обмотки постоянноми току, не более: 0.26 Ом; Допустимый ток обмотки: 850 мА; Диапазон рабочих температур: от -60 до +125 ℃; Упаковка: Катушка и лента; Типоразмер: 3216 (1206); Технология монтажа: SMT; Изготовитель: АО "НПО "ЭРКОН"
pins: 1, 2

## КИК-3216-120 нГн ±5% Зл
designator L?, comment 120 нГн ±5%  (value not drawn)
Катушка индуктивности с керамическим сердечником и золотым покрытием контактных площадок; Номиналиная индуктивность: 120 нГн; Добротность, не менее: 55; Резонансная частота, не менее: 1.10 ГГц; Сопротивление обмотки постоянноми току, не более: 0.26 Ом; Допустимый ток обмотки: 800 мА; Диапазон рабочих температур: от -60 до +125 ℃; Упаковка: Катушка и лента; Типоразмер: 3216 (1206); Технология монтажа: SMT; Изготовитель: АО "НПО "ЭРКОН"
pins: 1, 2

## КИК-3216-120 нГн ±10% Зл
designator L?, comment 120 нГн ±10%  (value not drawn)
Катушка индуктивности с керамическим сердечником и золотым покрытием контактных площадок; Номиналиная индуктивность: 120 нГн; Добротность, не менее: 60; Резонансная частота, не менее: 1.10 ГГц; Сопротивление обмотки постоянноми току, не более: 0.26 Ом; Допустимый ток обмотки: 800 мА; Диапазон рабочих температур: от -60 до +125 ℃; Упаковка: Катушка и лента; Типоразмер: 3216 (1206); Технология монтажа: SMT; Изготовитель: АО "НПО "ЭРКОН"
pins: 1, 2

## КИК-3216-150 нГн ±5% Зл
designator L?, comment 150 нГн ±5%  (value not drawn)
Катушка индуктивности с керамическим сердечником и золотым покрытием контактных площадок; Номиналиная индуктивность: 150 нГн; Добротность, не менее: 60; Резонансная частота, не менее: 0.95 ГГц; Сопротивление обмотки постоянноми току, не более: 0.31 Ом; Допустимый ток обмотки: 750 мА; Диапазон рабочих температур: от -60 до +125 ℃; Упаковка: Катушка и лента; Типоразмер: 3216 (1206); Технология монтажа: SMT; Изготовитель: АО "НПО "ЭРКОН"
pins: 1, 2

## КИК-3216-150 нГн ±10% Зл
designator L?, comment 150 нГн ±10%  (value not drawn)
Катушка индуктивности с керамическим сердечником и золотым покрытием контактных площадок; Номиналиная индуктивность: 150 нГн; Добротность, не менее: 60; Резонансная частота, не менее: 0.95 ГГц; Сопротивление обмотки постоянноми току, не более: 0.31 Ом; Допустимый ток обмотки: 750 мА; Диапазон рабочих температур: от -60 до +125 ℃; Упаковка: Катушка и лента; Типоразмер: 3216 (1206); Технология монтажа: SMT; Изготовитель: АО "НПО "ЭРКОН"
pins: 1, 2

## КИК-3216-180 нГн ±5% Зл
designator L?, comment 180 нГн ±5%  (value not drawn)
Катушка индуктивности с керамическим сердечником и золотым покрытием контактных площадок; Номиналиная индуктивность: 180 нГн; Добротность, не менее: 60; Резонансная частота, не менее: 0.90 ГГц; Сопротивление обмотки постоянноми току, не более: 0.43 Ом; Допустимый ток обмотки: 700 мА; Диапазон рабочих температур: от -60 до +125 ℃; Упаковка: Катушка и лента; Типоразмер: 3216 (1206); Технология монтажа: SMT; Изготовитель: АО "НПО "ЭРКОН"
pins: 1, 2

## КИК-3216-180 нГн ±10% Зл
designator L?, comment 180 нГн ±10%  (value not drawn)
Катушка индуктивности с керамическим сердечником и золотым покрытием контактных площадок; Номиналиная индуктивность: 180 нГн; Добротность, не менее: 60; Резонансная частота, не менее: 0.90 ГГц; Сопротивление обмотки постоянноми току, не более: 0.43 Ом; Допустимый ток обмотки: 700 мА; Диапазон рабочих температур: от -60 до +125 ℃; Упаковка: Катушка и лента; Типоразмер: 3216 (1206); Технология монтажа: SMT; Изготовитель: АО "НПО "ЭРКОН"
pins: 1, 2

## КИК-3216-220 нГн ±5% Зл
designator L?, comment 220 нГн ±5%  (value not drawn)
Катушка индуктивности с керамическим сердечником и золотым покрытием контактных площадок; Номиналиная индуктивность: 220 нГн; Добротность, не менее: 60; Резонансная частота, не менее: 0.76 ГГц; Сопротивление обмотки постоянноми току, не более: 0.50 Ом; Допустимый ток обмотки: 670 мА; Диапазон рабочих температур: от -60 до +125 ℃; Упаковка: Катушка и лента; Типоразмер: 3216 (1206); Технология монтажа: SMT; Изготовитель: АО "НПО "ЭРКОН"
pins: 1, 2

## КИК-3216-220 нГн ±10% Зл
designator L?, comment 220 нГн ±10%  (value not drawn)
Катушка индуктивности с керамическим сердечником и золотым покрытием контактных площадок; Номиналиная индуктивность: 220 нГн; Добротность, не менее: 60; Резонансная частота, не менее: 0.76 ГГц; Сопротивление обмотки постоянноми току, не более: 0.50 Ом; Допустимый ток обмотки: 670 мА; Диапазон рабочих температур: от -60 до +125 ℃; Упаковка: Катушка и лента; Типоразмер: 3216 (1206); Технология монтажа: SMT; Изготовитель: АО "НПО "ЭРКОН"
pins: 1, 2

## КИК-3216-270 нГн ±5% Зл
designator L?, comment 270 нГн ±5%  (value not drawn)
Катушка индуктивности с керамическим сердечником и золотым покрытием контактных площадок; Номиналиная индуктивность: 270 нГн; Добротность, не менее: 55; Резонансная частота, не менее: 0.73 ГГц; Сопротивление обмотки постоянноми току, не более: 0.56 Ом; Допустимый ток обмотки: 630 мА; Диапазон рабочих температур: от -60 до +125 ℃; Упаковка: Катушка и лента; Типоразмер: 3216 (1206); Технология монтажа: SMT; Изготовитель: АО "НПО "ЭРКОН"
pins: 1, 2

## КИК-3216-270 нГн ±10% Зл
designator L?, comment 270 нГн ±10%  (value not drawn)
Катушка индуктивности с керамическим сердечником и золотым покрытием контактных площадок; Номиналиная индуктивность: 270 нГн; Добротность, не менее: 55; Резонансная частота, не менее: 0.73 ГГц; Сопротивление обмотки постоянноми току, не более: 0.56 Ом; Допустимый ток обмотки: 630 мА; Диапазон рабочих температур: от -60 до +125 ℃; Упаковка: Катушка и лента; Типоразмер: 3216 (1206); Технология монтажа: SMT; Изготовитель: АО "НПО "ЭРКОН"
pins: 1, 2

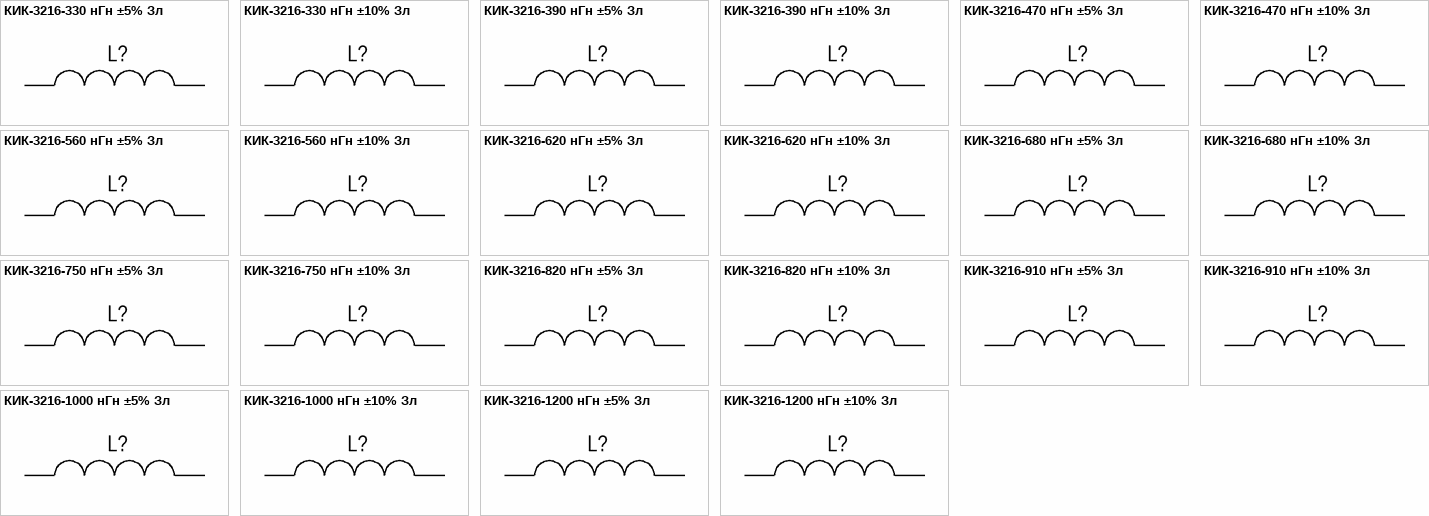
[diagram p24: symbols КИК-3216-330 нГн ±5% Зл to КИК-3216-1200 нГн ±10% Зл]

## КИК-3216-330 нГн ±5% Зл
designator L?, comment 330 нГн ±5%  (value not drawn)
Катушка индуктивности с керамическим сердечником и золотым покрытием контактных площадок; Номиналиная индуктивность: 330 нГн; Добротность, не менее: 45; Резонансная частота, не менее: 0.65 ГГц; Сопротивление обмотки постоянноми току, не более: 0.62 Ом; Допустимый ток обмотки: 590 мА; Диапазон рабочих температур: от -60 до +125 ℃; Упаковка: Катушка и лента; Типоразмер: 3216 (1206); Технология монтажа: SMT; Изготовитель: АО "НПО "ЭРКОН"
pins: 1, 2

## КИК-3216-330 нГн ±10% Зл
designator L?, comment 330 нГн ±10%  (value not drawn)
Катушка индуктивности с керамическим сердечником и золотым покрытием контактных площадок; Номиналиная индуктивность: 330 нГн; Добротность, не менее: 45; Резонансная частота, не менее: 0.65 ГГц; Сопротивление обмотки постоянноми току, не более: 0.62 Ом; Допустимый ток обмотки: 590 мА; Диапазон рабочих температур: от -60 до +125 ℃; Упаковка: Катушка и лента; Типоразмер: 3216 (1206); Технология монтажа: SMT; Изготовитель: АО "НПО "ЭРКОН"
pins: 1, 2

## КИК-3216-390 нГн ±5% Зл
designator L?, comment 390 нГн ±5%  (value not drawn)
Катушка индуктивности с керамическим сердечником и золотым покрытием контактных площадок; Номиналиная индуктивность: 390 нГн; Добротность, не менее: 45; Резонансная частота, не менее: 0.60 ГГц; Сопротивление обмотки постоянноми току, не более: 0.75 Ом; Допустимый ток обмотки: 530 мА; Диапазон рабочих температур: от -60 до +125 ℃; Упаковка: Катушка и лента; Типоразмер: 3216 (1206); Технология монтажа: SMT; Изготовитель: АО "НПО "ЭРКОН"
pins: 1, 2

## КИК-3216-390 нГн ±10% Зл
designator L?, comment 390 нГн ±10%  (value not drawn)
Катушка индуктивности с керамическим сердечником и золотым покрытием контактных площадок; Номиналиная индуктивность: 390 нГн; Добротность, не менее: 45; Резонансная частота, не менее: 0.60 ГГц; Сопротивление обмотки постоянноми току, не более: 0.75 Ом; Допустимый ток обмотки: 530 мА; Диапазон рабочих температур: от -60 до +125 ℃; Упаковка: Катушка и лента; Типоразмер: 3216 (1206); Технология монтажа: SMT; Изготовитель: АО "НПО "ЭРКОН"
pins: 1, 2

## КИК-3216-470 нГн ±5% Зл
designator L?, comment 470 нГн ±5%  (value not drawn)
Катушка индуктивности с керамическим сердечником и золотым покрытием контактных площадок; Номиналиная индуктивность: 470 нГн; Добротность, не менее: 45; Резонансная частота, не менее: 0.55ГГц; Сопротивление обмотки постоянноми току, не более: 1.30 Ом; Допустимый ток обмотки: 490 мА; Диапазон рабочих температур: от -60 до +125 ℃; Упаковка: Катушка и лента; Типоразмер: 3216 (1206); Технология монтажа: SMT; Изготовитель: АО "НПО "ЭРКОН"
pins: 1, 2

## КИК-3216-470 нГн ±10% Зл
designator L?, comment 470 нГн ±10%  (value not drawn)
Катушка индуктивности с керамическим сердечником и золотым покрытием контактных площадок; Номиналиная индуктивность: 470 нГн; Добротность, не менее: 45; Резонансная частота, не менее: 0.55ГГц; Сопротивление обмотки постоянноми току, не более: 1.30 Ом; Допустимый ток обмотки: 490 мА; Диапазон рабочих температур: от -60 до +125 ℃; Упаковка: Катушка и лента; Типоразмер: 3216 (1206); Технология монтажа: SMT; Изготовитель: АО "НПО "ЭРКОН"
pins: 1, 2

## КИК-3216-560 нГн ±5% Зл
designator L?, comment 560 нГн ±5%  (value not drawn)
Катушка индуктивности с керамическим сердечником и золотым покрытием контактных площадок; Номиналиная индуктивность: 560 нГн; Добротность, не менее: 45; Резонансная частота, не менее: 0.47 ГГц; Сопротивление обмотки постоянноми току, не более: 1.34 Ом; Допустимый ток обмотки: 460 мА; Диапазон рабочих температур: от -60 до +125 ℃; Упаковка: Катушка и лента; Типоразмер: 3216 (1206); Технология монтажа: SMT; Изготовитель: АО "НПО "ЭРКОН"
pins: 1, 2

## КИК-3216-560 нГн ±10% Зл
designator L?, comment 560 нГн ±10%  (value not drawn)
Катушка индуктивности с керамическим сердечником и золотым покрытием контактных площадок; Номиналиная индуктивность: 560 нГн; Добротность, не менее: 45; Резонансная частота, не менее: 0.47 ГГц; Сопротивление обмотки постоянноми току, не более: 1.34 Ом; Допустимый ток обмотки: 460 мА; Диапазон рабочих температур: от -60 до +125 ℃; Упаковка: Катушка и лента; Типоразмер: 3216 (1206); Технология монтажа: SMT; Изготовитель: АО "НПО "ЭРКОН"
pins: 1, 2

## КИК-3216-620 нГн ±5% Зл
designator L?, comment 620 нГн ±5%  (value not drawn)
Катушка индуктивности с керамическим сердечником и золотым покрытием контактных площадок; Номиналиная индуктивность: 620 нГн; Добротность, не менее: 45; Резонансная частота, не менее: 0.47 ГГц; Сопротивление обмотки постоянноми току, не более: 1.58 Ом; Допустимый ток обмотки: 460 мА; Диапазон рабочих температур: от -60 до +125 ℃; Упаковка: Катушка и лента; Типоразмер: 3216 (1206); Технология монтажа: SMT; Изготовитель: АО "НПО "ЭРКОН"
pins: 1, 2

## КИК-3216-620 нГн ±10% Зл
designator L?, comment 620 нГн ±10%  (value not drawn)
Катушка индуктивности с керамическим сердечником и золотым покрытием контактных площадок; Номиналиная индуктивность: 620 нГн; Добротность, не менее: 45; Резонансная частота, не менее: 0.47 ГГц; Сопротивление обмотки постоянноми току, не более: 1.58 Ом; Допустимый ток обмотки: 460 мА; Диапазон рабочих температур: от -60 до +125 ℃; Упаковка: Катушка и лента; Типоразмер: 3216 (1206); Технология монтажа: SMT; Изготовитель: АО "НПО "ЭРКОН"
pins: 1, 2

## КИК-3216-680 нГн ±5% Зл
designator L?, comment 680 нГн ±5%  (value not drawn)
Катушка индуктивности с керамическим сердечником и золотым покрытием контактных площадок; Номиналиная индуктивность: 680 нГн; Добротность, не менее: 45; Резонансная частота, не менее: 0.45 ГГц; Сопротивление обмотки постоянноми току, не более: 1.58 Ом; Допустимый ток обмотки: 430 мА; Диапазон рабочих температур: от -60 до +125 ℃; Упаковка: Катушка и лента; Типоразмер: 3216 (1206); Технология монтажа: SMT; Изготовитель: АО "НПО "ЭРКОН"
pins: 1, 2

## КИК-3216-680 нГн ±10% Зл
designator L?, comment 680 нГн ±10%  (value not drawn)
Катушка индуктивности с керамическим сердечником и золотым покрытием контактных площадок; Номиналиная индуктивность: 680 нГн; Добротность, не менее: 45; Резонансная частота, не менее: 0.45 ГГц; Сопротивление обмотки постоянноми току, не более: 1.58 Ом; Допустимый ток обмотки: 430 мА; Диапазон рабочих температур: от -60 до +125 ℃; Упаковка: Катушка и лента; Типоразмер: 3216 (1206); Технология монтажа: SMT; Изготовитель: АО "НПО "ЭРКОН"
pins: 1, 2

## КИК-3216-750 нГн ±5% Зл
designator L?, comment 750 нГн ±5%  (value not drawn)
Катушка индуктивности с керамическим сердечником и золотым покрытием контактных площадок; Номиналиная индуктивность: 750 нГн; Добротность, не менее: 45; Резонансная частота, не менее: 0.44 ГГц; Сопротивление обмотки постоянноми току, не более: 2.25 Ом; Допустимый ток обмотки: 320 мА; Диапазон рабочих температур: от -60 до +125 ℃; Упаковка: Катушка и лента; Типоразмер: 3216 (1206); Технология монтажа: SMT; Изготовитель: АО "НПО "ЭРКОН"
pins: 1, 2

## КИК-3216-750 нГн ±10% Зл
designator L?, comment 750 нГн ±10%  (value not drawn)
Катушка индуктивности с керамическим сердечником и золотым покрытием контактных площадок; Номиналиная индуктивность: 750 нГн; Добротность, не менее: 45; Резонансная частота, не менее: 0.44 ГГц; Сопротивление обмотки постоянноми току, не более: 2.25 Ом; Допустимый ток обмотки: 320 мА; Диапазон рабочих температур: от -60 до +125 ℃; Упаковка: Катушка и лента; Типоразмер: 3216 (1206); Технология монтажа: SMT; Изготовитель: АО "НПО "ЭРКОН"
pins: 1, 2

## КИК-3216-820 нГн ±5% Зл
designator L?, comment 820 нГн ±5%  (value not drawn)
Катушка индуктивности с керамическим сердечником и золотым покрытием контактных площадок; Номиналиная индуктивность: 820 нГн; Добротность, не менее: 45; Резонансная частота, не менее: 0.42 ГГц; Сопротивление обмотки постоянноми току, не более: 1.82 Ом; Допустимый ток обмотки: 400 мА; Диапазон рабочих температур: от -60 до +125 ℃; Упаковка: Катушка и лента; Типоразмер: 3216 (1206); Технология монтажа: SMT; Изготовитель: АО "НПО "ЭРКОН"
pins: 1, 2

## КИК-3216-820 нГн ±10% Зл
designator L?, comment 820 нГн ±10%  (value not drawn)
Катушка индуктивности с керамическим сердечником и золотым покрытием контактных площадок; Номиналиная индуктивность: 820 нГн; Добротность, не менее: 45; Резонансная частота, не менее: 0.42 ГГц; Сопротивление обмотки постоянноми току, не более: 1.82 Ом; Допустимый ток обмотки: 400 мА; Диапазон рабочих температур: от -60 до +125 ℃; Упаковка: Катушка и лента; Типоразмер: 3216 (1206); Технология монтажа: SMT; Изготовитель: АО "НПО "ЭРКОН"
pins: 1, 2

## КИК-3216-910 нГн ±5% Зл
designator L?, comment 910 нГн ±5%  (value not drawn)
Катушка индуктивности с керамическим сердечником и золотым покрытием контактных площадок; Номиналиная индуктивность: 910 нГн; Добротность, не менее: 45; Резонансная частота, не менее: 0.41 ГГц; Сопротивление обмотки постоянноми току, не более: 2.950 Ом; Допустимый ток обмотки: 310 мА; Диапазон рабочих температур: от -60 до +125 ℃; Упаковка: Катушка и лента; Типоразмер: 3216 (1206); Технология монтажа: SMT; Изготовитель: АО "НПО "ЭРКОН"
pins: 1, 2

## КИК-3216-910 нГн ±10% Зл
designator L?, comment 910 нГн ±10%  (value not drawn)
Катушка индуктивности с керамическим сердечником и золотым покрытием контактных площадок; Номиналиная индуктивность: 910 нГн; Добротность, не менее: 45; Резонансная частота, не менее: 0.41 ГГц; Сопротивление обмотки постоянноми току, не более: 2.950 Ом; Допустимый ток обмотки: 310 мА; Диапазон рабочих температур: от -60 до +125 ℃; Упаковка: Катушка и лента; Типоразмер: 3216 (1206); Технология монтажа: SMT; Изготовитель: АО "НПО "ЭРКОН"
pins: 1, 2

## КИК-3216-1000 нГн ±5% Зл
designator L?, comment 1000 нГн ±5%  (value not drawn)
Катушка индуктивности с керамическим сердечником и золотым покрытием контактных площадок; Добротность, не менее: 45; Резонансная частота, не менее: 0.40 ГГц; Сопротивление обмотки постоянноми току, не более: 2.80 Ом; Допустимый ток обмотки: 320 мА; Диапазон рабочих температур: от -60 до +125 ℃; Упаковка: Катушка и лента; Типоразмер: 3216 (1206); Технология монтажа: SMT; Изготовитель: АО "НПО "ЭРКОН"
pins: 1, 2

## КИК-3216-1000 нГн ±10% Зл
designator L?, comment 1000 нГн ±10%  (value not drawn)
Катушка индуктивности с керамическим сердечником и золотым покрытием контактных площадок; Добротность, не менее: 45; Резонансная частота, не менее: 0.40 ГГц; Сопротивление обмотки постоянноми току, не более: 2.80 Ом; Допустимый ток обмотки: 320 мА; Диапазон рабочих температур: от -60 до +125 ℃; Упаковка: Катушка и лента; Типоразмер: 3216 (1206); Технология монтажа: SMT; Изготовитель: АО "НПО "ЭРКОН"
pins: 1, 2

## КИК-3216-1200 нГн ±5% Зл
designator L?, comment 1200 нГн ±5%  (value not drawn)
Катушка индуктивности с керамическим сердечником и золотым покрытием контактных площадок; Добротность, не менее: 45; Резонансная частота, не менее: 0.38 ГГц; Сопротивление обмотки постоянноми току, не более: 3.20 Ом; Допустимый ток обмотки: 300 мА; Диапазон рабочих температур: от -60 до +125 ℃; Упаковка: Катушка и лента; Типоразмер: 3216 (1206); Технология монтажа: SMT; Изготовитель: АО "НПО "ЭРКОН"
pins: 1, 2

## КИК-3216-1200 нГн ±10% Зл
designator L?, comment 1200 нГн ±10%  (value not drawn)
Катушка индуктивности с керамическим сердечником и золотым покрытием контактных площадок; Добротность, не менее: 45; Резонансная частота, не менее: 0.38 ГГц; Сопротивление обмотки постоянноми току, не более: 3.20 Ом; Допустимый ток обмотки: 300 мА; Диапазон рабочих температур: от -60 до +125 ℃; Упаковка: Катушка и лента; Типоразмер: 3216 (1206); Технология монтажа: SMT; Изготовитель: АО "НПО "ЭРКОН"
pins: 1, 2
